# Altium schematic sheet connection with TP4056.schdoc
size 238 x 171 mm
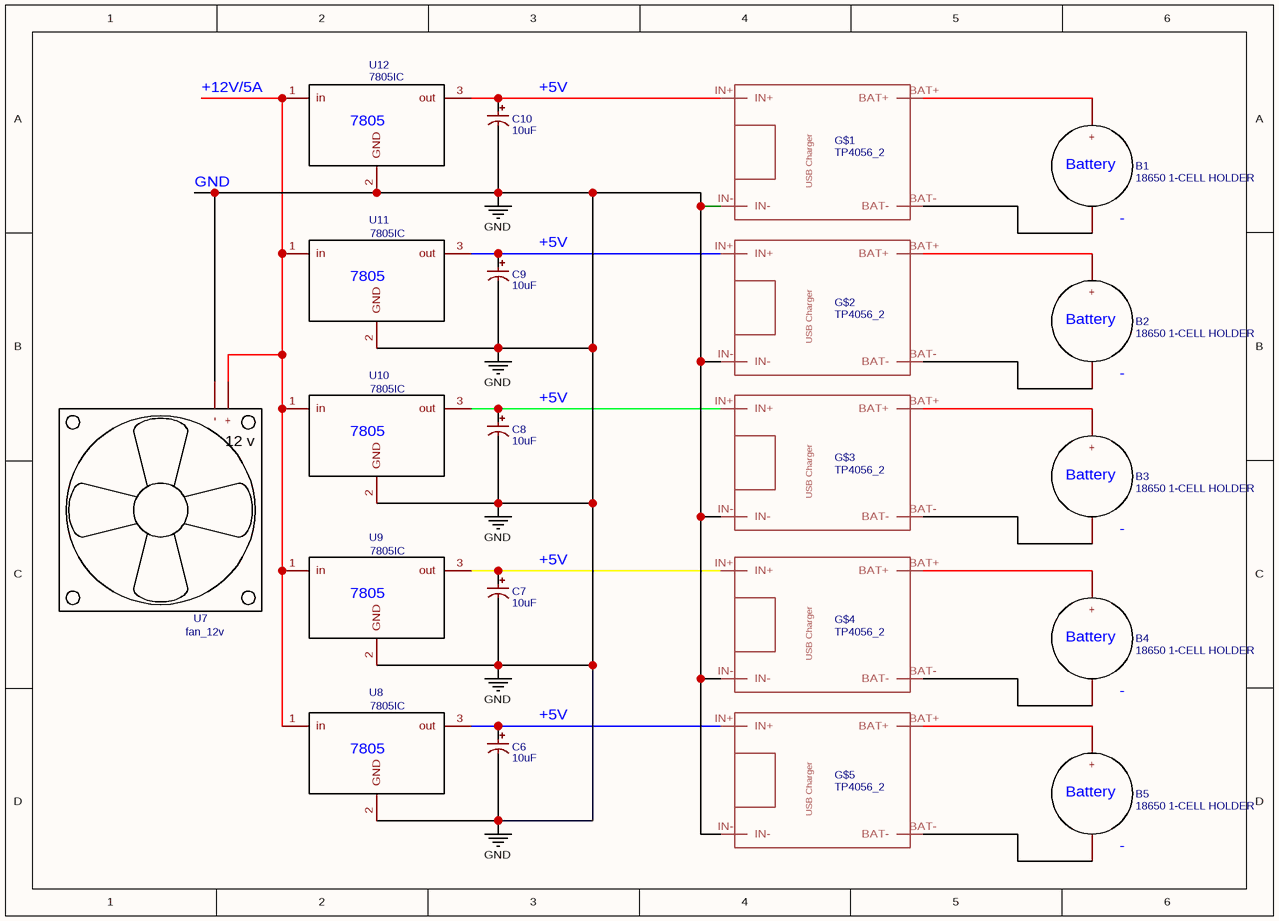
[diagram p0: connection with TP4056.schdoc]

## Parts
B1  18650 1-CELL HOLDER  [18650 1-CELL HOLDER]
B2  18650 1-CELL HOLDER  [18650 1-CELL HOLDER]
B3  18650 1-CELL HOLDER  [18650 1-CELL HOLDER]
B4  18650 1-CELL HOLDER  [18650 1-CELL HOLDER]
B5  18650 1-CELL HOLDER  [18650 1-CELL HOLDER]
C6  10uF  [CAPACITOR1000UF16V]
C7  10uF  [CAPACITOR1000UF16V]
C8  10uF  [CAPACITOR1000UF16V]
C9  10uF  [CAPACITOR1000UF16V]
C10  10uF  [CAPACITOR1000UF16V]
G$1  TP4056_2  [TP4056]
G$2  TP4056_2  [TP4056]
G$3  TP4056_2  [TP4056]
G$4  TP4056_2  [TP4056]
G$5  TP4056_2  [TP4056]
U7  fan_12v  [12V FAN]
U8  7805IC  [7805]
U9  7805IC  [7805]
U10  7805IC  [7805]
U11  7805IC  [7805]
U12  7805IC  [7805]

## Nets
GND: C6.2(-) C7.2(-) C8.2(-) C9.2(-) C10.2(-) G$1.IN- G$2.IN- G$3.IN- G$4.IN- G$5.IN- U7.2(-) U8.2(GND) U9.2(GND) U10.2(GND) U11.2(GND) U12.2(GND)
NetB1_1: B1.1(+) G$1.BAT+
NetB1_2: B1.2(-) G$1.BAT-
NetB2_1: B2.1(+) G$2.BAT+
NetB2_2: B2.2(-) G$2.BAT-
NetB3_1: B3.1(+) G$3.BAT+
NetB3_2: B3.2(-) G$3.BAT-
NetB4_1: B4.1(+) G$4.BAT+
NetB4_2: B4.2(-) G$4.BAT-
NetB5_1: B5.1(+) G$5.BAT+
NetB5_2: B5.2(-) G$5.BAT-
NetC6_1: C6.1(+) G$5.IN+ U8.3(out)
NetC7_1: C7.1(+) G$4.IN+ U9.3(out)
NetC8_1: C8.1(+) G$3.IN+ U10.3(out)
NetC9_1: C9.1(+) G$2.IN+ U11.3(out)
NetC10_1: C10.1(+) G$1.IN+ U12.3(out)
NetU7_1: U7.1(+) U8.1(in) U9.1(in) U10.1(in) U11.1(in) U12.1(in)

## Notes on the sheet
- +12V/5A
- (near C10) +5V
- GND
- (near C9) +5V
- (near C8) +5V
- (near C7) +5V
- (near C6) +5V

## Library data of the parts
B1-B5 = 18650 1-CELL HOLDER: BOM_Manufacturer Part: Battery_holder_18650; Contributor: Visionz
C6-C10 = 10uF: BOM_Manufacturer: ValuePro; BOM_Manufacturer Part: electrolytic capacitor10UF50V; nameAlias: Capacitance
G$1-G$5 = TP4056_2: Contributor: zillawilli
U7 = fan_12v: Contributor: ozgural
U8-U12 = 7805IC: Contributor: 53024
